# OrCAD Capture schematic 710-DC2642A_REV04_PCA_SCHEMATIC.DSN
size Custom; note: 2.5A SUPERCAPACITOR BACKUP POWER MANAGER
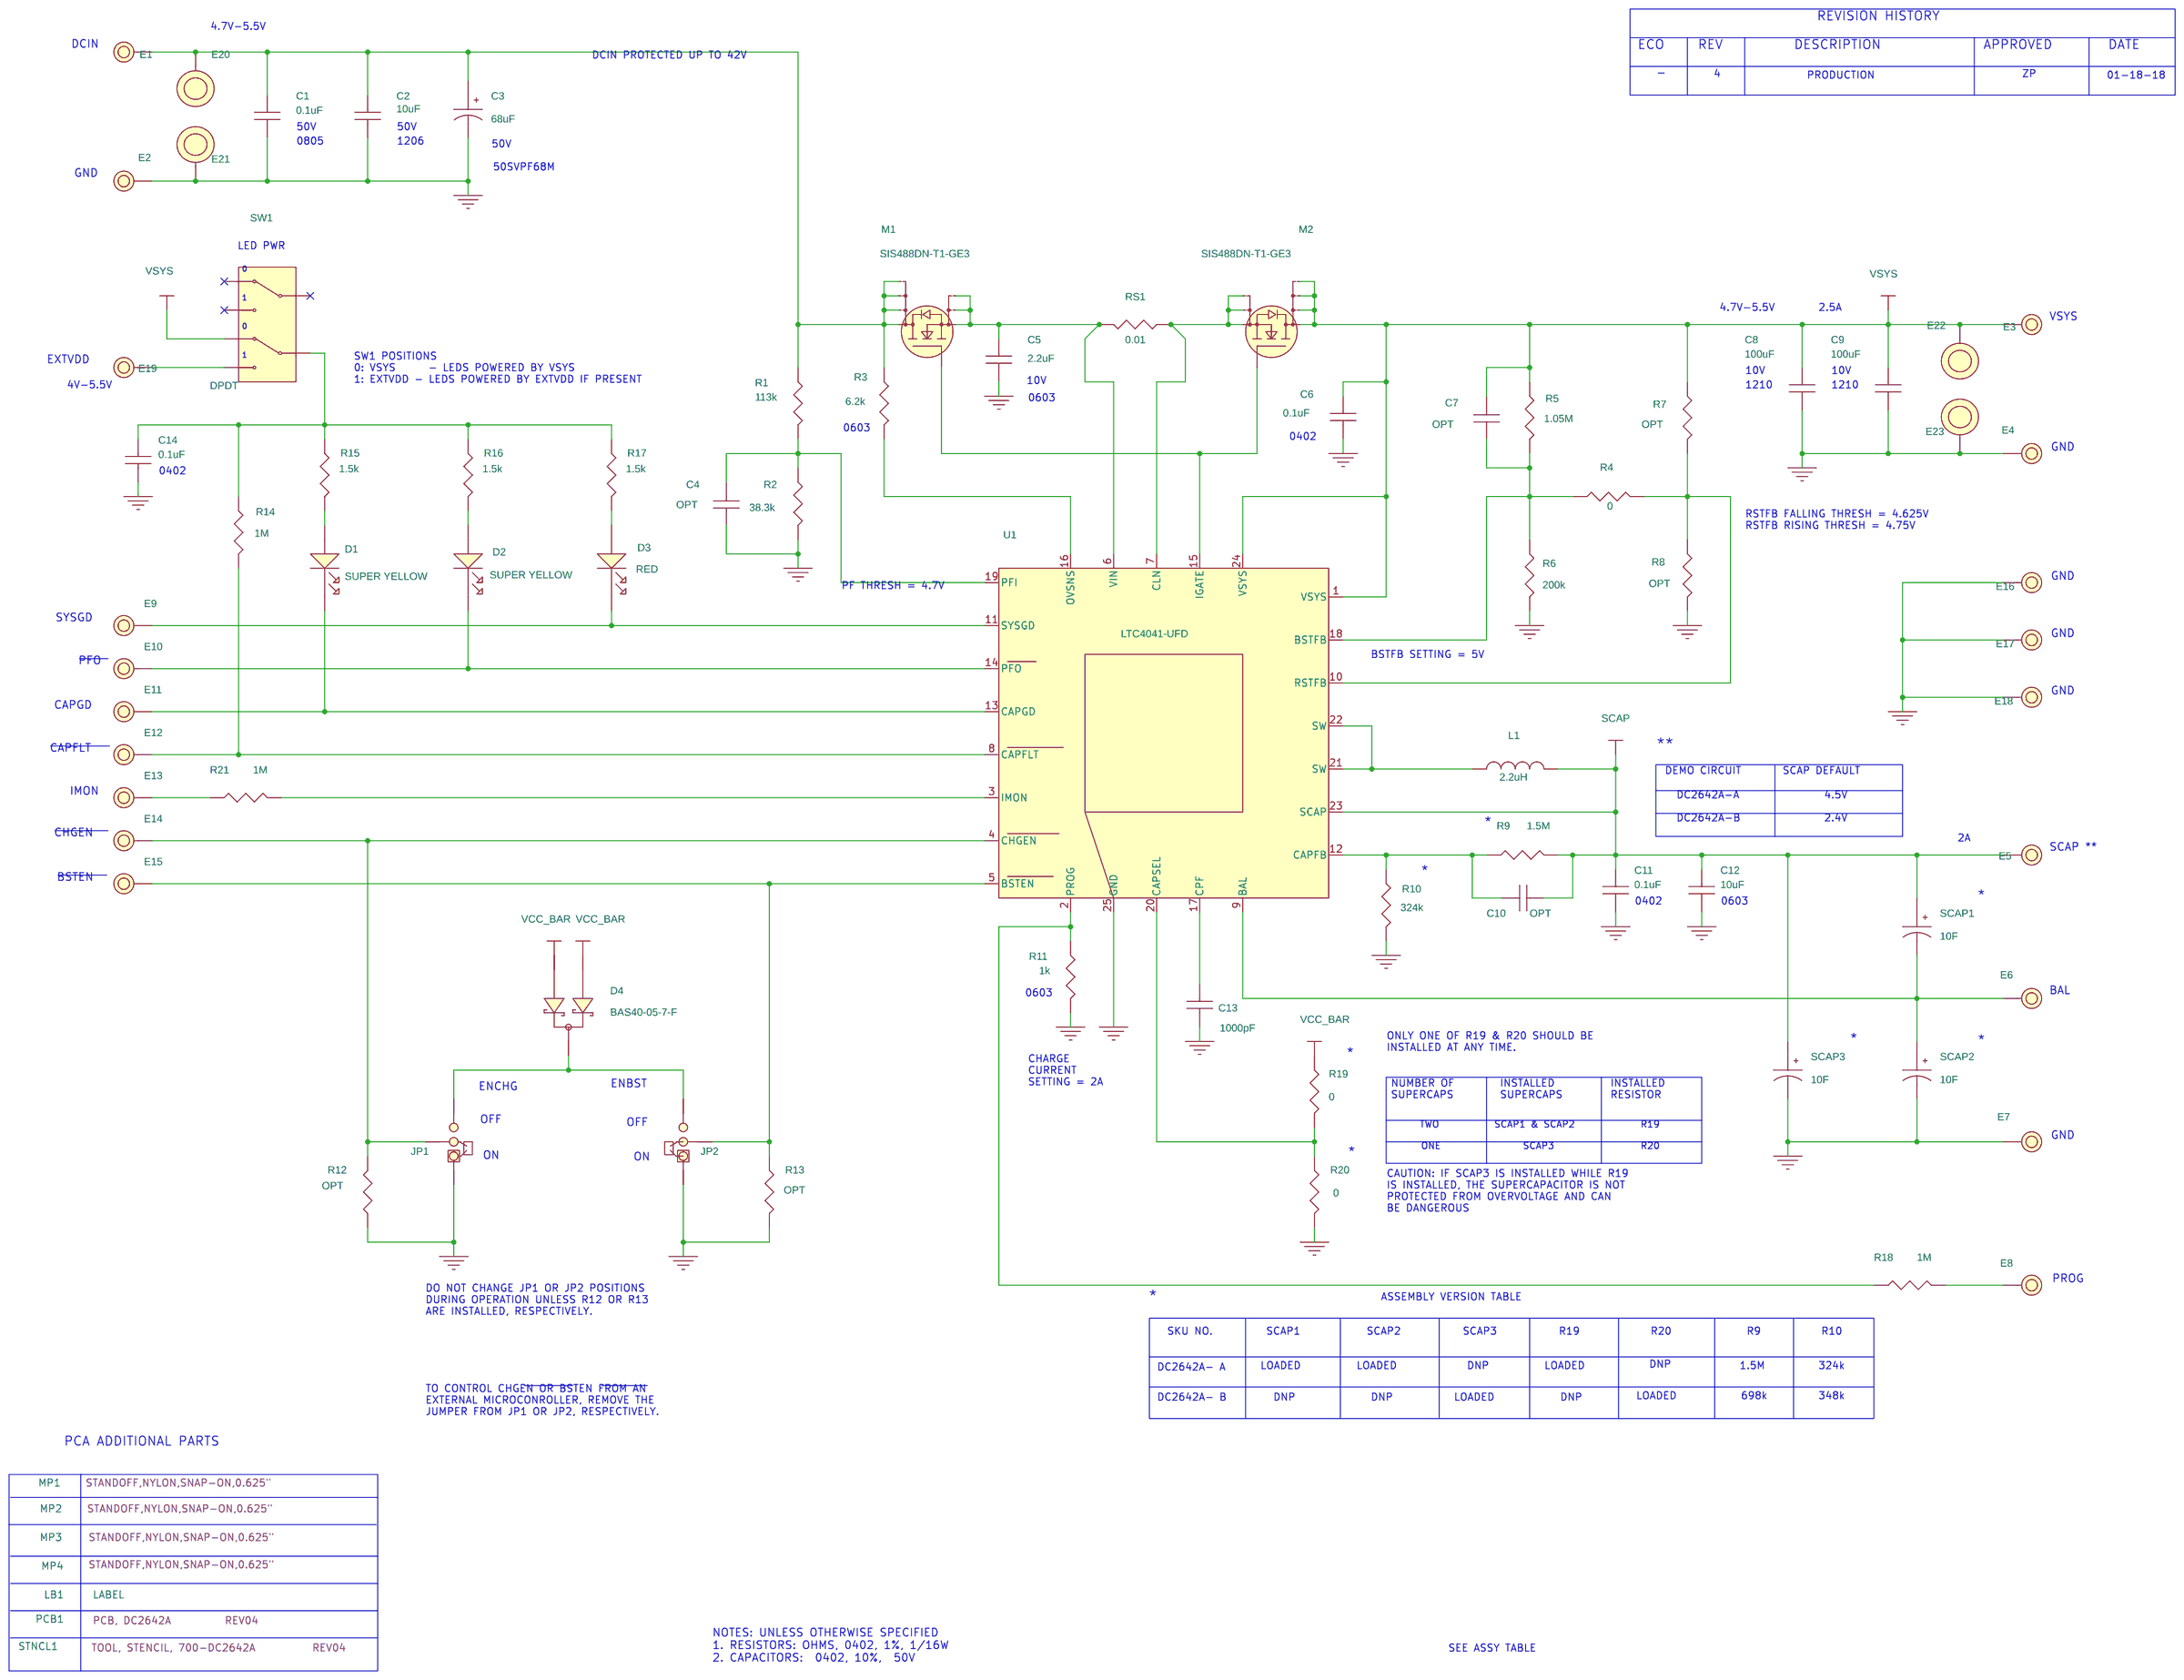
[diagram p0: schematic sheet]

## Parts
C1  0.1uF  [CC0805M]
C2  10uF  [CC1206M]
C3  68uF  [PANASONIC_SVPF_10X12.6]
C4  OPT  [CC0402N]
C5  2.2uF  [CC0603M]
C6  0.1uF  [CC0402N]
C7  OPT  [CC0402N]
C8  100uF  [CC1210M]
C9  100uF  [CC1210M]
C10  OPT  [CC0402N]
C11  0.1uF  [CC0402N]
C12  10uF  [CC0603M]
C13  1000pF  [CC0402N]
C14  0.1uF  [CC0402N]
D1  SUPER YELLOW  [LED-SML-LX0603SYW-TR]
D2  SUPER YELLOW  [LED-SML-LX0603SYW-TR]
D3  RED  [LED-LTST-C193KRKT-5A]
D4  BAS40-05-7-F  [SOT23-3M]
E1  TEST POINT  [MILLMAX2501]
E2  TEST POINT  [MILLMAX2501]
E3  TEST POINT  [MILLMAX2501]
E4  TEST POINT  [MILLMAX2501]
E5  TEST POINT  [MILLMAX2501]
E6  TEST POINT  [MILLMAX2501]
E7  TEST POINT  [MILLMAX2501]
E8  TEST POINT  [MILLMAX2501]
E9  TEST POINT  [MILLMAX2501]
E10  TEST POINT  [MILLMAX2501]
E11  TEST POINT  [MILLMAX2501]
E12  TEST POINT  [MILLMAX2501]
E13  TEST POINT  [MILLMAX2501]
E14  TEST POINT  [MILLMAX2501]
E15  TEST POINT  [MILLMAX2501]
E16  TEST POINT  [MILLMAX2501]
E17  TEST POINT  [MILLMAX2501]
E18  TEST POINT  [MILLMAX2501]
E19  TEST POINT  [MILLMAX2501]
E20  BANANA JACK  [KEY-575-4]
E21  BANANA JACK  [KEY-575-4]
E22  BANANA JACK  [KEY-575-4]
E23  BANANA JACK  [KEY-575-4]
JP1  HDR  [HD1X3-079]
JP2  HDR  [HD1X3-079]
L1  2.2uH  [COILCRAFT-XAL50]
LB1  LABEL  [895-0154_REV01]
M1  SIS488DN-T1-GE3  [POWERPAK1212-8S]
M2  SIS488DN-T1-GE3  [POWERPAK1212-8S]
MP1  STANDOFF  [KEYSTONE_8829-8834]
MP2  STANDOFF  [KEYSTONE_8829-8834]
MP3  STANDOFF  [KEYSTONE_8829-8834]
MP4  STANDOFF  [KEYSTONE_8829-8834]
PCB1  PCB, DC2642A
R1  113k  [CR0402N]
R2  38.3k  [CR0402N]
R3  6.2k  [CR0603M]
R4  0  [CR0402N]
R5  1.05M  [CR0402N]
R6  200k  [CR0402N]
R7  OPT  [CR0402N]
R8  OPT  [CR0402N]
R9  1.5M  [CR0402N]
R10  324k  [CR0402N]
R11  1k  [CR0603M]
R12  OPT  [CR0603M]
R13  OPT  [CR0603M]
R14  1M  [CR0402N]
R15  1.5k  [CR0402N]
R16  1.5k  [CR0402N]
R17  1.5k  [CR0402N]
R18  1M  [CR0402N]
R19  0  [CR0603N]
R20  0  [CR0603N]
R21  1M  [CR0402N]
RS1  0.01  [RES-PRL0816]
SCAP1  10F  [CAP-ESHSR-0010-0050C0-002R7]
SCAP2  10F  [CAP-ESHSR-0010-0050C0-002R7]
SCAP3  10F  [CAP-ESHSR-0010-0050C0-002R7]
STNCL1  TOOL, STENCIL, 700-DC2642A
SW1  DPDT  [C&K-JS202011CQN]
U1  LTC4041-UFD  [LTC-UFD-24-1696]
XJP1  SHUNT
XJP2  SHUNT

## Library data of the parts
C1 = CAP: CAP.,0.1uF,X7R,50V,10%,0805; CLASS: DISCRETE; Dielectric Type: X7R; FPLIST: CC0805N,CC0805L,CC0805M; Manufacturer: AVX; Manufacturer PN: 08055C104KAT2A; PART_NUMBER: 150-3458; Package Size: 0805; Rated Voltage: 50V; Tolerance: 10%; UserField01: Thickness=0.50mm
C2 = CAP: CAP.,10uF,X5R,50V,10%,1206; CLASS: DISCRETE; Dielectric Type: X5R; FPLIST: CC1206N,CC1206L,CC1206M; Manufacturer: MURATA; Manufacturer PN: GRM31CR61H106KA12L; PART_NUMBER: 150-0330; Package Size: 1206; Rated Voltage: 50V; Tolerance: 10%
C3 = CAP_P_ALT: CAP.,68uF,ALUM POLY,50V,20%,SMD 10.0mmX12.6mm, F12; CLASS: DISCRETE; Dielectric Type: ALUM POLY; Manufacturer: PANASONIC; Manufacturer PN: 50SVPF68M; PART_NUMBER: 150-2486; Package Size: SMD 10.0mmX12.6mm, F12; Package Type: Radial; Rated Voltage: 50V; Tolerance: 20%
C4 C7 C10 = CAP: CAP., OPTION, 0402; CLASS: DISCRETE; FPLIST: CC0402N,CC0402L,CC0402M; PART_NUMBER: 150-3148; Package Size: 0402; Package Type: SMD
C5 = CAP: CAP.,2.2uF,X5R,10V,10%,0603,NO SUBS. ALLOWED; CLASS: DISCRETE; Dielectric Type: X5R; FPLIST: CC0603N,CC0603L,CC0603M; Manufacturer: MURATA; Manufacturer PN: GRM188R61A225KE34D; PART_NUMBER: 150-0168; Package Size: 0603; Package Type: SMD; Rated Voltage: 10V; Tolerance: 10%; UserField01: NO SUBS. ALLOWED
C6 C11 C14 = CAP: CAP.,0.1uF,X7R,10V,10%,0402; CLASS: DISCRETE; Dielectric Type: X7R; FPLIST: CC0402N,CC0402L,CC0402M; Manufacturer: MURATA; Manufacturer PN: GRM155R71A104KA01D; PART_NUMBER: 150-0331; Package Size: 0402; Rated Voltage: 10V; Tolerance: 10%
C8 C9 = CAP: CAP.,100uF,X5R,10V,20%,1210,NO SUBS. ALLOWED; CLASS: DISCRETE; Dielectric Type: X5R; FPLIST: CC1210N,CC1210L,CC1210M; Manufacturer: MURATA; Manufacturer PN: GRM32ER61A107ME20L; PART_NUMBER: 150-3207; Package Size: 1210; Rated Voltage: 10V; Tolerance: 20%; UserField01: NO SUBS. ALLOWED
C12 = CAP: CAP.,10uF,X5R,10V,20%,0603; CLASS: DISCRETE; Dielectric Type: X5R; FPLIST: CC0603N,CC0603L,CC0603M; Manufacturer: AVX; Manufacturer PN: 0603ZD106MAT2A; PART_NUMBER: 150-3459; Package Size: 0603; Package Type: SMD; Rated Voltage: 10V; Tolerance: 20%
C13 = CAP: CAP.,1000pF,X7R,16V,10%,0402; CLASS: DISCRETE; Dielectric Type: X7R; FPLIST: CC0402N,CC0402L,CC0402M; Manufacturer: AVX; Manufacturer PN: 0402YC102KAT2A; PART_NUMBER: 150-3197; Package Size: 0402; Rated Voltage: 16V; Tolerance: 10%
D1 D2 = LED_ALT: LED,SUPER YELLOW,MILKY WHITE DIFF.,0603; CLASS: DISCRETE; Manufacturer: LUMEX; Manufacturer PN: SML-LX0603SYW-TR; PART_NUMBER: 270-0090; Package Size: 0603 (1608 Metric); Package Type: 0603
D3 = LED_ALT: LED,RED,WATER CLEAR,0603; CLASS: DISCRETE; FPLIST: LED-LTST-C193KRKT-5A,LED_0603,LED-LTST-C193KRKT-5A; Manufacturer: LITE-ON TECHNOLOGY CORP.; Manufacturer PN: LTST-C193KRKT-5A; PART_NUMBER: 270-0070; Package Size: 0603 (1608 Metric); Package Type: 0603
D4 = DIODE_SCHOTTKY_SOT_ARRAY_2: DIODE,SCHOTTKY,40V,200mA,SOT23-3; CLASS: DISCRETE; FPLIST: SOT23-3N,SOT23-3L,SOT23-3M; Manufacturer: DIODES INC.; PART_NUMBER: 210-0302; Package Type: SOT23-3; Rated Voltage: 40V
E1-E19 = TESTPOINT_.219_MILL-MAX_2501: TEST POINT,TURRET,0.094",MTG. HOLE; CLASS: IO; Manufacturer: MILL-MAX; Manufacturer PN: 2501-2-00-80-00-00-07-0; PART_NUMBER: 260-0003
E20-E23 = BANANA_KEYSTONE-575-4: CONN.,BANANA JACK,FEMALE,THT,NON-INSULATED, SWAGE; CLASS: IO; Manufacturer: KEYSTONE; Manufacturer PN: 575-4; PART_NUMBER: 250-0428
JP1 JP2 = 1X3_C: CONN.,HDR,MALE,1x3,2mm,STR, THT,NO SUBS. ALLOWED; CLASS: IO; Manufacturer: Wurth Elektronik; Manufacturer PN: 62000311121; PART_NUMBER: 250-0639
L1 = IND_ALT: IND.,2.2uH,PWR,20%,9.2A,14.5mOHMS,5.48mmX5.28mm, XAL5030,AEC-Q200; CLASS: DISCRETE; FPLIST: COILCRAFT-XAL50,IND-XAL5030; Manufacturer: COILCRAFT; Manufacturer PN: XAL5030-222MEB; PART_NUMBER: 200-0261; Package Size: 5.48mmX5.28mm, XAL5030; Tolerance: 20%
LB1 = BLANK_LABEL: LABEL SPEC, DEMO BOARD SERIAL NUMBER; Manufacturer: BRADY; Manufacturer PN: THT-96-717-10; PART_NUMBER: 895-0154
M1 M2 = SIS488DN-T1-GE3: XSTR.,MOSFET, N-CH,40V,40A,PowerPAK1212-8; CLASS: DISCRETE; Manufacturer: VISHAY; Manufacturer PN: SiS488DN-T1-GE3; PART_NUMBER: 240-0309; Package Type: PowerPAK1212-8; Rated Power: 52W; Rated Voltage: 40V
MP1-MP4 = BLANK_PINLESS_MECHANICAL_PART: STANDOFF,NYLON,SNAP-ON,0.625"; CLASS: DISCRETE; Manufacturer: KEYSTONE; Manufacturer PN: 8834; PART_NUMBER: 763-0013
PCB1 = BLANK_PCB_PART: BOM Notes: REV04; CLASS: DISCRETE; Manufacturer: EAGLE ELECTRONICS INC.; Manufacturer PN: 600-DC2642A; PART_NUMBER: 600-DC2642A
R1 = RES: RES.,AEC-Q200,113k OHMS,1%,1/10W,0402; CLASS: DISCRETE; FPLIST: CR0402N,CR0402L,CR0402M; Manufacturer: PANASONIC; Manufacturer PN: ERJ2RKF1133X; PART_NUMBER: 100-0267; Package Size: 0402; Rated Power: 1/10W; Temperature Coefficient: 100ppm/C; Tolerance: 1%
R2 = RES: RES.,AEC-Q200,38.3k OHMS,1%,1/16W,0402; CLASS: DISCRETE; Manufacturer: VISHAY; Manufacturer PN: CRCW040238K3FKED; PART_NUMBER: 100-0968; Package Size: 0402; Rated Power: 1/16W; Temperature Coefficient: 100ppm; Tolerance: 1%
R3 = RES: RES.,Anti-Surge, AEC-Q200,6.2k OHMS,5%,1/4W,0603; CLASS: DISCRETE; Manufacturer: ROHM; Manufacturer PN: ESR03EZPJ622; PART_NUMBER: 100-0969; Package Size: 0603; Rated Power: 1/4W; Temperature Coefficient: 200ppm; Tolerance: 5%
R4 = RES: RES.,0 OHM,1/16W,0402; CLASS: DISCRETE; Manufacturer: ROHM; Manufacturer PN: MCR01MZPJ000; PART_NUMBER: 100-0025; Package Size: 0402; Rated Power: 1/16W
R5 = RES: RES.,AEC-Q200,1.05M OHMS,1%,1/16W,0402; CLASS: DISCRETE; FPLIST: CR0402N,CR0402L,CR0402M; Manufacturer: VISHAY; Manufacturer PN: CRCW04021M05FKED; PART_NUMBER: 100-0541; Package Size: 0402; Rated Power: 1/16W; Temperature Coefficient: 100ppm; Tolerance: 1%
R6 = RES: RES.,200k OHMS,1%,1/16W,0402; CLASS: DISCRETE; FPLIST: CR0402N,CR0402L,CR0402M; Manufacturer: PANASONIC; Manufacturer PN: ERJ2RKF2003X; PART_NUMBER: 100-0329; Package Size: 0402; Rated Power: 1/16W; Temperature Coefficient: 100ppm/C; Tolerance: 1%
R7 R8 = RES: RES., OPTION, 0402; CLASS: DISCRETE; PART_NUMBER: 100-0357; Package Size: 0402
R9 = RES: RES.,AEC-Q200,1.5M OHMS,1%,1/16W,0402; CLASS: DISCRETE; FPLIST: CR0402N,CR0402L,CR0402M; Manufacturer: VISHAY; Manufacturer PN: CRCW04021M50FKED; PART_NUMBER: 100-2349; Package Size: 0402; Rated Power: 1/16W; Temperature Coefficient: 100ppm/C; Tolerance: 1%
R10 = RES: RES.,324k OHMS,1%,1/16W,0402; CLASS: DISCRETE; Manufacturer: NIC; Manufacturer PN: NRC04F3243TRF; PART_NUMBER: 100-0394; Package Size: 0402; Rated Power: 1/16W; Tolerance: 1%
R11 = RES: RES.,1k OHMS,1%,1/10W,0603; CLASS: DISCRETE; FPLIST: CR0603N,CR0603L,CR0603M; Manufacturer: VISHAY; Manufacturer PN: CRCW06031K00FKEA; PART_NUMBER: 100-2422; Package Size: 0603; Rated Power: 1/10W; Temperature Coefficient: 100ppm; Tolerance: 1%
R12 R13 = RES: RES., OPTION, 0603; CLASS: DISCRETE; FPLIST: CR0603N,CR0603L,CR0603M; PART_NUMBER: 100-2374; Package Size: 0603
R14 R18 R21 = RES: RES.,AEC-Q200,1M OHM,1%,1/16W,0402; CLASS: DISCRETE; FPLIST: CR0402N,CR0402L,CR0402M; Manufacturer: VISHAY; Manufacturer PN: CRCW04021M00FKED; PART_NUMBER: 100-2457; Package Size: 0402; Rated Power: 1/16W; Temperature Coefficient: 100ppm; Tolerance: 1%
R15-R17 = RES: RES.,1.5k OHMS,1%,1/16W,0402; CLASS: DISCRETE; FPLIST: CR0402N,CR0402L,CR0402M; Manufacturer: NIC; Manufacturer PN: NRC04F1501TRF; PART_NUMBER: 100-2689; Package Size: 0402; Rated Power: 1/16W; Temperature Coefficient: 100ppm; Tolerance: 1%
R19 R20 = RES: RES.,0 OHM,1/10W,0603; CLASS: DISCRETE; FPLIST: CR0603N,CR0603L,CR0603M; Manufacturer: YAGEO; Manufacturer PN: RC0603FR-070RL; PART_NUMBER: 100-2621; Package Size: 0603; Rated Power: 1/10W
RS1 = RES: RES.,SENSE,0.01 OHM,1%,1/3W,0603; CLASS: DISCRETE; Manufacturer: SUSUMU; Manufacturer PN: PRL0816-R010-F-T1; PART_NUMBER: 100-0490; Package Size: 0603; Rated Power: 1/3W; Temperature Coefficient: 0 to 330ppm; Tolerance: 1%
SCAP1-SCAP3 = CAP_P_ALT: CAP.,10F,ULTRA,2.7V,-10/+20%,THT,RADIAL; CLASS: DISCRETE; Dielectric Type: ULTRA; Manufacturer: NESSCAP CO. LTD.; Manufacturer PN: ESHSR-0010C0-002R7; PART_NUMBER: 150-0245; Package Size: THT; Rated Voltage: 2.7V; Tolerance: -10/+20%; UserField01: RADIAL
STNCL1 = BLANK_STENCIL_PART: BOM Notes: REV04; CLASS: DISCRETE; Manufacturer: LINEAR TECH.; Manufacturer PN: 830-DC2642A; PART_NUMBER: 830-DC2642A
SW1 = SW-DPDT-JS202011CQN: SWITCH,SLIDE,DPDT,0.3A,6VDC,PTH; CLASS: DISCRETE; Manufacturer: C&K; Manufacturer PN: JS202011CQN; PART_NUMBER: 430-0039
U1 = LTC4041-UFD: IC,2.5A Supercap Backup Pwr Mngr,QFN-24 (4mmX5mm); CLASS: IC; Manufacturer: LINEAR TECH.; Manufacturer PN: LTC4041EUFD#PBF; PART_NUMBER: LTC4041EUFD#PBF; Package Type: QFN-24 (4mmX5mm); Supply Voltage: 35V
XJP1 XJP2 = SHUNT_2MM_D: CONN.,SHUNT,FEMALE,2 POS,2mm; CLASS: IO; Manufacturer: Wurth Elektronik; Manufacturer PN: 60800213421; PART_NUMBER: 250-0485

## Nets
GND: C1.2 C2.2 C3.2 C4.1 C5.2 C6.2 C8.2 C9.2 C11.2 C12.2 C13.2 C14.2 E2.1 E4.1 E7.1 E16.1 E17.1 E18.1 E21.1 E23.1 JP1.1 JP2.1 R2.2 R6.1 R8.2 R10.2 R11.2 R12.2 R13.2 R20.2 SCAP2.2 SCAP3.2 U1.25(GND)
SCAP: C10.1 C11.1 C12.1 D4.1 E5.1 L1.2 R9.2 SCAP1.1 SCAP3.1 U1.23(SCAP)
VSYS: C6.1 C7.2 C8.1 C9.1 D4.2 E3.1 E22.1 M2.5(D) M2.6(Dtab) M2.7(Dtab1) M2.8(Dtab2) R5.1 R7.1 R19.1 SW1.4 U1.1(VSYS) U1.24(VSYS)
N17026716: C1.1 C2.1 C3.1 E1.1 E20.1 M1.5(D) M1.6(Dtab) M1.7(Dtab1) M1.8(Dtab2) R1.1 R3.1
N17179515: C4.2 R1.2 R2.1 U1.19(PFI)
N17179785: R3.2 U1.16(OVSNS)
N17179940: C5.1 M1.1(S) M1.2(Stab) M1.3(Stab1) RS1.1 U1.6(VIN)
N17180763: M1.4(G) M2.4(G) U1.15(IGATE)
N17181264: M2.1(S) M2.2(Stab) M2.3(Stab1) RS1.2 U1.7(CLN)
N17183077: C7.1 R4.1 R5.2 R6.2 U1.18(BSTFB)
N17183295: R4.2 R7.2 R8.1 U1.10(RSTFB)
N17185384: L1.1 U1.21(SW) U1.22(SW)
N17185453: C10.2 R9.1 R10.1 U1.12(CAPFB)
N17186246: E6.1 SCAP1.2 SCAP2.1 U1.9(BAL)
N17186593: C13.1 U1.17(CPF)
N17187068: R19.2 R20.1 U1.20(CAPSEL)
N17187189: R11.1 R18.1 U1.2(PROG)
N17187598: D3.1(CATHODE) E9.1 U1.11(SYSGD)
N17187601: D2.1(CATHODE) E10.1 U1.14(PFO)
N17187604: D1.1(CATHODE) E11.1 U1.13(CAPGD)
N17187607: E12.1 R14.2 U1.8(CAPFLT)
N17187610: R21.2 U1.3(IMON)
N17187613: E14.1 JP1.2 R12.1 U1.4(CHGEN)
N17187622: E15.1 JP2.2 R13.1 U1.5(BSTEN)
N17191514: C14.1 R14.1 R15.1 R16.1 R17.1 SW1.5
N17191598: D1.2(ANODE) R15.2
N17267461: D3.2(ANODE) R17.2
N17270137: E19.1 SW1.6
N17271566: E8.1 R18.2
N17285675: D2.2(ANODE) R16.2
N17293846: D4.3 JP1.3 JP2.3
N17315442: E13.1 R21.1

Not connected (* = marked no-connect by the designer): SW1 1* 2* 3*

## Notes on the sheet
- REVISION HISTORY
- 4.7V-5.5V
- DCIN
- ECO
- REV
- DESCRIPTION
- APPROVED
- DATE
- DCIN PROTECTED UP TO 42V
- -
- 4
- PRODUCTION
- ZP
- 01-18-18
- 50V
- 50V
- 0805
- 1206
- 50V
- 50SVPF68M
- GND
- LED PWR
- 0
- 1
- 4.7V-5.5V        2.5A
- VSYS
- 0
- 1
- SW1 POSITIONS
  0: VSYS      - LEDS POWERED BY VSYS
  1: EXTVDD - LEDS POWERED BY EXTVDD IF PRESENT
- EXTVDD
- 10V
- 10V
- 4V-5.5V
- 10V
- 1210
- 1210
- 0603
- 0603
- 0402
- GND
- 0402
- RSTFB FALLING THRESH = 4.625V
  RSTFB RISING THRESH = 4.75V
- GND
- PF THRESH = 4.7V
- SYSGD
- GND
- PFO
- BSTFB SETTING = 5V
- GND
- CAPGD
- **
- CAPFLT
- DEMO CIRCUIT
- SCAP DEFAULT
- IMON
- DC2642A-A
- 4.5V
- *
- DC2642A-B
- 2.4V
- CHGEN
- 2A
- SCAP **
- BSTEN
- *
- *
- 0402
- 0603
- 0603
- BAL
- *
- ONLY ONE OF R19 & R20 SHOULD BE
  INSTALLED AT ANY TIME.
- *
- *
- CHARGE
  CURRENT
  SETTING = 2A
- ENCHG
- ENBST
- NUMBER OF
  SUPERCAPS
- INSTALLED
  SUPERCAPS
- INSTALLED
  RESISTOR
- OFF
- OFF
- TWO
- SCAP1 & SCAP2
- R19
- GND
- *
- ONE
- SCAP3
- R20
- ON
- ON
- CAUTION: IF SCAP3 IS INSTALLED WHILE R19
  IS INSTALLED, THE SUPERCAPACITOR IS NOT
  PROTECTED FROM OVERVOLTAGE AND CAN
  BE DANGEROUS
- DO NOT CHANGE JP1 OR JP2 POSITIONS
  DURING OPERATION UNLESS R12 OR R13
  ARE INSTALLED, RESPECTIVELY.
- PROG
- *
- ASSEMBLY VERSION TABLE
- SKU NO.
- SCAP1
- SCAP2
- SCAP3
- R19
- R20
- R9
- R10
- DC2642A- A
- LOADED
- LOADED
- DNP
- LOADED
- DNP
- 1.5M
- 324k
- TO CONTROL CHGEN OR BSTEN FROM AN
  EXTERNAL MICROCONROLLER, REMOVE THE
  JUMPER FROM JP1 OR JP2, RESPECTIVELY.
- DC2642A- B
- DNP
- DNP
- LOADED
- DNP
- LOADED
- 698k
- 348k
- PCA ADDITIONAL PARTS
- NOTES: UNLESS OTHERWISE SPECIFIED
  1. RESISTORS: OHMS, 0402, 1%, 1/16W
  2. CAPACITORS:  0402, 10%,  50V
- SEE ASSY TABLE
